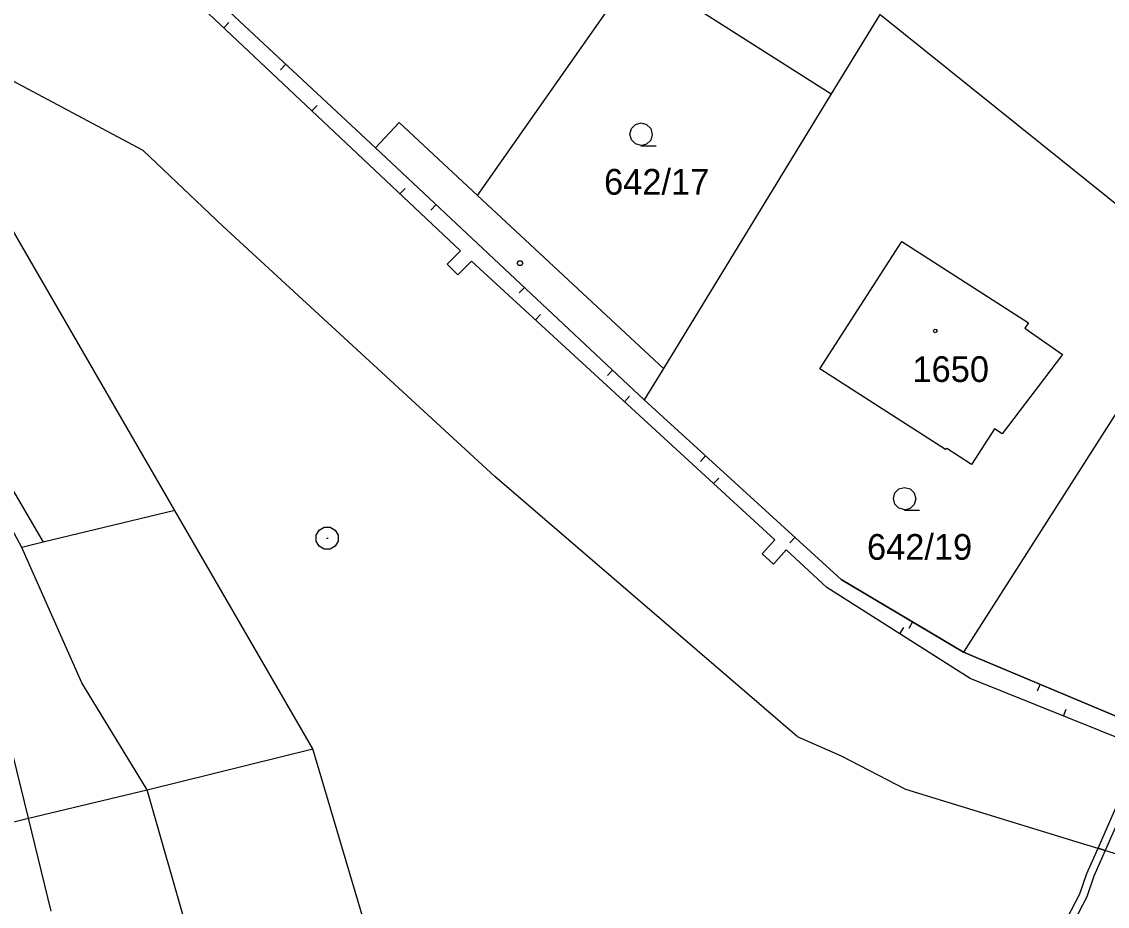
# Model space of a CAD drawing. Extents: x -777309 to -774195, y -1144706 to -1143600.
# Drawn here: x -774359.9 to -774288.1, y -1144564.6 to -1144506.1 of the extents above; entities that cross this region are included whole.
import ezdxf

# ---------------------------------------------------------------- set-up
doc = ezdxf.new("R2010")
doc.units = 0
for name, color, linetype in [('1', 7, 'Continuous'), ('12', 7, 'Continuous'), ('13', 7, 'Continuous'), ('2', 7, 'Continuous'), ('3', 7, 'Continuous'), ('4', 7, 'Continuous'), ('5', 7, 'Continuous'), ('8', 7, 'Continuous')]:
    doc.layers.add(name, color=color, linetype=linetype)

msp = doc.modelspace()

# ---------------------------------------------------------------- linework, layer by layer
at = {"layer": '1'}
for p, q in [((-774329.73, -1144517.56), (-774319.27, -1144502.61)), ((-774319.27, -1144502.61), (-774306.37, -1144510.83)), ((-774336.49, -1144514.4), (-774346.44, -1144505.12)), ((-774303.15, -1144505.58), (-774306.37, -1144510.83)), ((-774281.71, -1144522.82), (-774303.15, -1144505.58)), ((-774351.85, -1144514.58), (-774366.28, -1144506.89)), ((-774349.75, -1144538.38), (-774367.58, -1144507.56)), ((-774306.37, -1144510.83), (-774317.45, -1144528.99)), ((-774346.57, -1144519.59), (-774351.85, -1144514.58)), ((-774318.72, -1144531.06), (-774336.49, -1144514.4)), ((-774317.45, -1144528.99), (-774329.73, -1144517.56)), ((-774328.59, -1144536.14), (-774346.57, -1144519.59)), ((-774307.11, -1144529.01), (-774301.7, -1144520.59)), ((-774301.7, -1144520.59), (-774293.32, -1144525.98)), ((-774281.71, -1144522.82), (-774297.62, -1144547.75)), ((-774293.32, -1144525.98), (-774293.56, -1144526.34)), ((-774293.56, -1144526.34), (-774291.08, -1144528.07)), ((-774291.08, -1144528.07), (-774295.06, -1144533.31)), ((-774317.45, -1144528.99), (-774318.72, -1144531.06)), ((-774298.8, -1144534.35), (-774307.11, -1144529.01)), ((-774305.71, -1144542.95), (-774318.72, -1144531.06)), ((-774295.56, -1144532.98), (-774297.08, -1144535.34)), ((-774295.06, -1144533.31), (-774295.56, -1144532.98)), ((-774298.72, -1144534.28), (-774298.8, -1144534.35)), ((-774297.08, -1144535.34), (-774298.72, -1144534.28)), ((-774308.6, -1144553.33), (-774328.59, -1144536.14)), ((-774349.75, -1144538.38), (-774358.44, -1144540.48)), ((-774340.62, -1144554.15), (-774349.75, -1144538.38)), ((-774359.86, -1144540.83), (-774360.52, -1144539.6)), ((-774358.44, -1144540.48), (-774359.86, -1144540.83)), ((-774297.62, -1144547.75), (-774305.71, -1144542.95)), ((-774285.44, -1144552.89), (-774297.62, -1144547.75)), ((-774308.6, -1144553.33), (-774305.7, -1144554.61)), ((-774351.57, -1144556.86), (-774340.62, -1144554.15)), ((-774334.94, -1144573.27), (-774340.62, -1144554.15)), ((-774305.7, -1144554.61), (-774301.44, -1144556.83)), ((-774359.43, -1144558.74), (-774351.57, -1144556.86)), ((-774301.44, -1144556.83), (-774290.19, -1144560.28)), ((-774357.92, -1144564.89), (-774359.43, -1144558.74)), ((-774290.19, -1144560.28), (-774281.77, -1144562.84))]:
    msp.add_line(p, q, dxfattribs=at)
at = {"layer": '12'}
for p, q in [((-774307.11, -1144529.01), (-774301.7, -1144520.59)), ((-774301.7, -1144520.59), (-774293.32, -1144525.98)), ((-774293.32, -1144525.98), (-774293.56, -1144526.34)), ((-774293.56, -1144526.34), (-774291.08, -1144528.07)), ((-774291.08, -1144528.07), (-774295.06, -1144533.31)), ((-774298.8, -1144534.35), (-774307.11, -1144529.01)), ((-774295.56, -1144532.98), (-774297.08, -1144535.34)), ((-774295.06, -1144533.31), (-774295.56, -1144532.98)), ((-774298.72, -1144534.28), (-774298.8, -1144534.35)), ((-774297.08, -1144535.34), (-774298.72, -1144534.28))]:
    msp.add_line(p, q, dxfattribs=at)
at = {"layer": '13'}
for p, q in [((-774330.87, -1144521.22), (-774350.54, -1144502.67)), ((-774346.44, -1144505.12), (-774336.49, -1144514.4)), ((-774346.512, -1144506.469), (-774346.168, -1144506.105)), ((-774342.418, -1144508.871), (-774342.759, -1144509.237)), ((-774340.691, -1144511.958), (-774340.348, -1144511.594)), ((-774336.49, -1144514.4), (-774318.72, -1144531.06)), ((-774334.871, -1144517.446), (-774334.528, -1144517.083)), ((-774332.478, -1144518.162), (-774332.82, -1144518.527)), ((-774331.75, -1144522.09), (-774330.87, -1144521.22)), ((-774331.04, -1144522.8), (-774331.75, -1144522.09)), ((-774330.14, -1144521.9), (-774331.04, -1144522.8)), ((-774310.08, -1144540.33), (-774330.14, -1144521.9)), ((-774326.641, -1144523.633), (-774326.983, -1144523.998)), ((-774325.912, -1144525.784), (-774325.574, -1144525.416)), ((-774320.805, -1144529.105), (-774321.147, -1144529.47)), ((-774320.021, -1144531.197), (-774319.683, -1144530.828)), ((-774318.72, -1144531.06), (-774305.71, -1144542.95)), ((-774314.66, -1144534.77), (-774314.997, -1144535.14)), ((-774314.13, -1144536.609), (-774313.792, -1144536.241)), ((-774310.93, -1144541.26), (-774310.08, -1144540.33)), ((-774308.755, -1144540.167), (-774309.092, -1144540.537)), ((-774310.18, -1144541.94), (-774310.93, -1144541.26)), ((-774309.34, -1144541), (-774310.18, -1144541.94)), ((-774306.64, -1144543.49), (-774309.34, -1144541)), ((-774305.71, -1144542.95), (-774297.62, -1144547.75)), ((-774297.18, -1144549.51), (-774306.64, -1144543.49)), ((-774301.82, -1144546.557), (-774301.552, -1144546.135)), ((-774300.98, -1144545.756), (-774301.235, -1144546.187)), ((-774297.62, -1144547.75), (-774285.44, -1144552.89)), ((-774285.9, -1144554.04), (-774297.18, -1144549.51)), ((-774292.553, -1144549.888), (-774292.747, -1144550.349)), ((-774291.004, -1144551.99), (-774290.818, -1144551.526))]:
    msp.add_line(p, q, dxfattribs=at)
msp.add_lwpolyline([(-774286.99, -1144552.24), (-774286.31, -1144554.16), (-774285.56, -1144554.27), (-774285.78, -1144555.3), (-774288.24, -1144560.87), (-774288.72, -1144560.73), (-774286.3, -1144555.24), (-774286.68, -1144554.58), (-774287.41, -1144554.24), (-774287.07, -1144553.51), (-774287.46, -1144552.41), (-774287.56, -1144552)], close=True, dxfattribs=at)
for points in [[(-774336.59, -1144567.7), (-774336.74, -1144567.22), (-774334.21, -1144566.72), (-774325.31, -1144565.88), (-774322.64, -1144565.67), (-774319.43, -1144565.78), (-774316.82, -1144566.03), (-774311.23, -1144567.41), (-774304.02, -1144569.13), (-774298.51, -1144570.94), (-774296.8, -1144571.4), (-774296.61, -1144570.78), (-774295.71, -1144570.07), (-774294.47, -1144569.35), (-774292.7, -1144568.02), (-774291.02, -1144565.87), (-774289.92, -1144563.75), (-774289.46, -1144562.4), (-774288.72, -1144560.73), (-774288.24, -1144560.87)], [(-774288.24, -1144560.87), (-774289, -1144562.58), (-774289.46, -1144563.95), (-774290.6, -1144566.15), (-774292.34, -1144568.38), (-774294.19, -1144569.77), (-774295.37, -1144570.45)]]:
    msp.add_lwpolyline(points, dxfattribs=at)
at = {"layer": '3'}
for points in [[(-774318.92, -1144514.24), (-774319.3, -1144514.14), (-774319.57, -1144513.87), (-774319.67, -1144513.5), (-774319.57, -1144513.13), (-774319.3, -1144512.86), (-774318.93, -1144512.76), (-774318.56, -1144512.86), (-774318.29, -1144513.13), (-774318.19, -1144513.51), (-774318.29, -1144513.89), (-774318.56, -1144514.16), (-774318.94, -1144514.26), (-774317.94, -1144514.26)], [(-774301.5, -1144538.34), (-774301.88, -1144538.24), (-774302.15, -1144537.97), (-774302.25, -1144537.6), (-774302.15, -1144537.23), (-774301.88, -1144536.96), (-774301.51, -1144536.86), (-774301.14, -1144536.96), (-774300.87, -1144537.23), (-774300.77, -1144537.61), (-774300.87, -1144537.99), (-774301.14, -1144538.26), (-774301.52, -1144538.36), (-774300.52, -1144538.36)]]:
    msp.add_lwpolyline(points, dxfattribs=at)
at = {"layer": '4'}
for p, q in [((-774334.92, -1144512.73), (-774336.49, -1144514.4)), ((-774329.73, -1144517.56), (-774334.92, -1144512.73)), ((-774373.38, -1144515.01), (-774358.44, -1144540.48)), ((-774355.9, -1144549.8), (-774359.86, -1144540.83)), ((-774351.57, -1144556.86), (-774355.9, -1144549.8)), ((-774359.43, -1144558.74), (-774361.23, -1144551.36)), ((-774346.09, -1144576.1), (-774351.57, -1144556.86)), ((-774394.44, -1144567.3), (-774359.43, -1144558.74))]:
    msp.add_line(p, q, dxfattribs=at)
at = {"layer": '5'}
for points in [[(-774326.84, -1144521.88), (-774326.75, -1144522.03), (-774326.84, -1144522.18), (-774327.02, -1144522.18), (-774327.11, -1144522.03), (-774327.02, -1144521.88)], [(-774299.48, -1144526.406), (-774299.413, -1144526.42), (-774299.379, -1144526.48), (-774299.366, -1144526.52), (-774299.379, -1144526.58), (-774299.433, -1144526.627), (-774299.48, -1144526.634), (-774299.54, -1144526.614), (-774299.58, -1144526.574), (-774299.594, -1144526.52), (-774299.58, -1144526.46), (-774299.527, -1144526.413)]]:
    msp.add_lwpolyline(points, close=True, dxfattribs=at)
at = {"layer": '8'}
msp.add_line((-774339.72, -1144540.22), (-774339.62, -1144540.22), dxfattribs=at)
msp.add_lwpolyline([(-774339.48, -1144539.5), (-774339.14, -1144539.69), (-774338.95, -1144540.03), (-774338.95, -1144540.42), (-774339.14, -1144540.76), (-774339.48, -1144540.95), (-774339.87, -1144540.95), (-774340.21, -1144540.76), (-774340.4, -1144540.42), (-774340.4, -1144540.03), (-774340.21, -1144539.69), (-774339.87, -1144539.5)], close=True, dxfattribs=at)

# ---------------------------------------------------------------- texts
at = {"layer": '2'}
for s, p in [('642/17', (-774321.373, -1144517.5)), ('1650', (-774300.987, -1144529.89)), ('642/19', (-774303.993, -1144541.65))]:
    msp.add_text(s, height=1.7, dxfattribs=at).set_placement(p)

doc.saveas('drawing.dxf')
